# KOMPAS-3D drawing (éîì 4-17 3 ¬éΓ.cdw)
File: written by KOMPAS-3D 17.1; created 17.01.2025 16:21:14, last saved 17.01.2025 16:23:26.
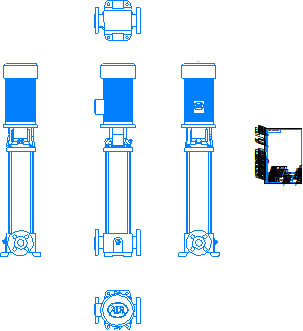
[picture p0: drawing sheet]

Sheet 1: A4, portrait

Title block, sheet 1: name: ВМН 4-15 3 кВт; designation: ВМН 4-15 3 кВт; material: Сталь 10  ГОСТ 1050-2013; mass: 145,05; sheets: 1; sheet format: A4; stored path: \\adlc.lan\data\АДЛ_ПКД\3D-модели\ADL production\Насосы ГРАНПАМП\Насосы ВМН\ВМН4\KOMPAS 3D\ВМН 4-17 3 кВт.cdw

Views: Вид 1, Спереди, Проекционный вид 2, Проекционный вид 3, Проекционный вид 4, Проекционный вид 5
Referenced files in \\adlc.lan\data\АДЛ_ПКД\3D-модели\ADL production\Насосы ГРАНПАМП\Насосы ВМН\ВМН4\KOMPAS 3D\: ВМН 4-17 3 кВт.m3d
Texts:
  Andrey
  АДЛ
Dimensions and other numbers on the sheet: 1:1; 1; 145,05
